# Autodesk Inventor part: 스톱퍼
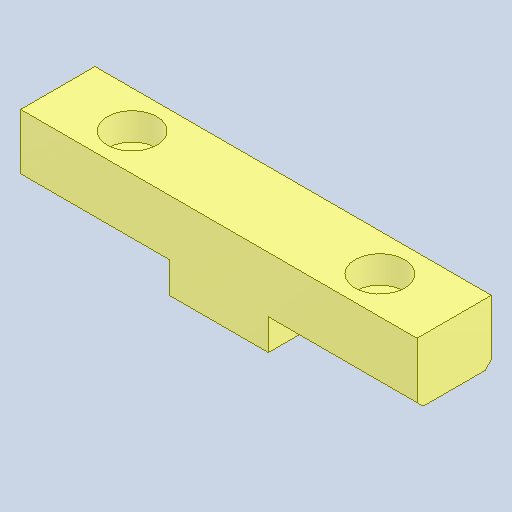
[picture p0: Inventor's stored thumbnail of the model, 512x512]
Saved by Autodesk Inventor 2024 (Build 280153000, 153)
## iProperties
Created: 2024-10
Part Number: 스톱퍼
Material: 강철, 연강
Document SubType Name: Modeling
Designer: user
Density: 7.85 g/cm^3
Appearance: 기본값
Author: jhkim
Sending System: Autodesk Inventor 2025
Preprocessor: ST-DEVELOPER v20
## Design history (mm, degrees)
feature "솔리드1"
node "솔리드2"
